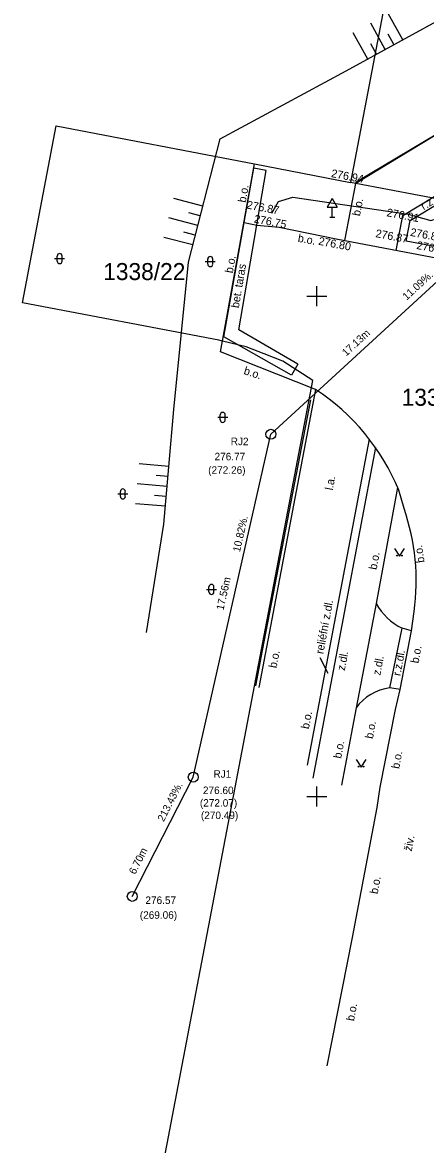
# Model space of a CAD drawing. Extents: x -601602 to -600882, y -1162594 to -1161950.
# Drawn here: x -601289.7 to -601269.6, y -1162117.4 to -1162061.3 of the extents above; entities that cross this region are included whole.
import ezdxf

# ---------------------------------------------------------------- set-up
doc = ezdxf.new("R2010")
doc.units = 0
for name, color, linetype in [('G_ZNACKY', 7, 'Continuous'), ('H_VYSKY_PREVZATE', 7, 'Continuous'), ('IS_KAN_JEDNOTNA', 7, 'Continuous'), ('IS_VO_PRELOZKA', 7, 'Continuous'), ('KN_Hranice parcel', 7, 'Continuous'), ('KN_Parcelní čísla', 7, 'Continuous'), ('Vrstva 14', 7, 'Continuous'), ('Vrstva 19', 7, 'Continuous'), ('Vrstva 22', 7, 'Continuous'), ('Vrstva 49', 7, 'Continuous'), ('Vrstva 7', 7, 'Continuous'), ('X_SOUR_KRIZKY_SEVER', 7, 'Continuous')]:
    doc.layers.add(name, color=color, linetype=linetype)

# ---------------------------------------------------------------- blocks, each defined once
blk = doc.blocks.new('POINT_DISPLAY')
blk.add_line((0, 0), (0, 0))

msp = doc.modelspace()

# ---------------------------------------------------------------- linework, layer by layer
at = {"layer": 'G_ZNACKY'}
for centre in [(-601277.302, -1162081.896), (-601281.181, -1162099.025), (-601284.233, -1162104.983)]:
    msp.add_circle(centre, 0.25, dxfattribs=at)
at = {"layer": 'IS_KAN_JEDNOTNA'}
msp.add_lwpolyline([(-601284.233, -1162104.983), (-601281.181, -1162099.025), (-601277.302, -1162081.896), (-601264.676, -1162070.309), (-601240.903, -1162074.739), (-601224.554, -1162077.728), (-601180.153, -1162087.436), (-601164.522, -1162091.613), (-601134.295, -1162101.261)], dxfattribs=at)
at = {"layer": 'IS_VO_PRELOZKA'}
msp.add_lwpolyline([(-601277.25, -1162070.85), (-601276.92, -1162070.27), (-601276.21, -1162070.04), (-601270.43, -1162070.89), (-601269.3, -1162071.21), (-601267.85, -1162070.76), (-601267.85, -1162070.76), (-601265.6, -1162071.22), (-601262.94, -1162071.88), (-601254.87, -1162073.2), (-601250.35, -1162073.86), (-601249.7, -1162074.36), (-601250.2, -1162075.96), (-601249.52, -1162074.33), (-601248.79, -1162074.18), (-601240.94, -1162075.85), (-601238.61, -1162076.29), (-601226.51, -1162078.06), (-601223.39, -1162080.54), (-601226.51, -1162078.06), (-601238.61, -1162076.29), (-601238.61, -1162076.29)], dxfattribs=at)
at = {"layer": 'KN_Hranice parcel'}
for p, q in [((-601266.06, -1162031.27), (-601273.32, -1162069.31)), ((-601279.72, -1162077.24), (-601278.12, -1162068.39)), ((-601278.12, -1162068.39), (-601273.32, -1162069.31)), ((-601273.06, -1162069.36), (-601273.32, -1162069.31)), ((-601265.78, -1162070.75), (-601273.06, -1162069.36))]:
    msp.add_line(p, q, dxfattribs=at)
for points in [[(-601238.38, -1162068.56), (-601263.78, -1162063.75), (-601273.06, -1162069.36)], [(-601279.72, -1162077.24), (-601279.91, -1162077.2), (-601289.73, -1162075.33), (-601288.05, -1162066.49), (-601278.12, -1162068.39)], [(-601288.12, -1162146.84), (-601275.21, -1162079.21), (-601276.71, -1162078.25), (-601277.63, -1162077.88), (-601278.53, -1162077.52), (-601279.72, -1162077.24)]]:
    msp.add_lwpolyline(points, dxfattribs=at)
at = {"layer": 'Vrstva 14'}
for p, q in [((-601287.993, -1162073.242), (-601287.993, -1162072.992)), ((-601287.743, -1162073.242), (-601287.743, -1162072.992)), ((-601288.118, -1162073.117), (-601287.618, -1162073.117)), ((-601280.586, -1162073.262), (-601280.086, -1162073.262)), ((-601280.461, -1162073.387), (-601280.461, -1162073.137)), ((-601280.211, -1162073.387), (-601280.211, -1162073.137)), ((-601279.835, -1162081.172), (-601279.835, -1162080.922)), ((-601279.585, -1162081.172), (-601279.585, -1162080.922)), ((-601279.96, -1162081.047), (-601279.46, -1162081.047)), ((-601284.832, -1162085.001), (-601284.832, -1162084.751)), ((-601284.582, -1162085.001), (-601284.582, -1162084.751)), ((-601284.957, -1162084.876), (-601284.457, -1162084.876)), ((-601271.12, -1162087.605), (-601270.87, -1162087.979)), ((-601270.87, -1162087.979), (-601270.62, -1162087.605)), ((-601280.526, -1162089.645), (-601280.026, -1162089.645)), ((-601280.401, -1162089.77), (-601280.401, -1162089.52)), ((-601280.151, -1162089.77), (-601280.151, -1162089.52)), ((-601273.037, -1162098.146), (-601272.787, -1162098.52)), ((-601272.787, -1162098.52), (-601272.537, -1162098.146))]:
    msp.add_line(p, q, dxfattribs=at)
for points in [[(-601270.995, -1162087.98), (-601271.02, -1162087.955), (-601270.995, -1162087.93)], [(-601270.995, -1162087.98), (-601270.995, -1162087.93), (-601270.97, -1162087.955)], [(-601270.745, -1162087.98), (-601270.77, -1162087.955), (-601270.745, -1162087.93)], [(-601270.745, -1162087.98), (-601270.745, -1162087.93), (-601270.72, -1162087.955)], [(-601272.912, -1162098.521), (-601272.937, -1162098.496), (-601272.912, -1162098.471)], [(-601272.912, -1162098.521), (-601272.912, -1162098.471), (-601272.887, -1162098.496)], [(-601272.662, -1162098.521), (-601272.687, -1162098.496), (-601272.662, -1162098.471)], [(-601272.662, -1162098.521), (-601272.662, -1162098.471), (-601272.637, -1162098.496)]]:
    msp.add_lwpolyline(points, close=True, dxfattribs=at)
for centre, start, end in [((-601287.868, -1162072.992), 0, 180), ((-601280.335, -1162073.139), 0, 180), ((-601287.868, -1162073.242), 180, 360), ((-601280.335, -1162073.389), 180, 360), ((-601279.709, -1162080.924), 0, 180), ((-601279.709, -1162081.174), 180, 360), ((-601284.705, -1162084.751), 0, 180), ((-601284.705, -1162085.001), 180, 360), ((-601280.275, -1162089.522), 0, 180), ((-601280.275, -1162089.772), 180, 360)]:
    msp.add_arc(centre, 0.125, start, end, dxfattribs=at)
at = {"layer": 'Vrstva 19'}
for p, q in [((-601274.23, -1162070.117), (-601274.48, -1162070.55)), ((-601274.23, -1162070.117), (-601273.98, -1162070.55)), ((-601274.48, -1162070.55), (-601273.98, -1162070.55)), ((-601274.23, -1162071.05), (-601274.23, -1162070.55)), ((-601274.355, -1162071.05), (-601274.105, -1162071.05))]:
    msp.add_line(p, q, dxfattribs=at)
at = {"layer": 'Vrstva 22'}
msp.add_line((-601277.74, -1162092.69), (-601278.074, -1162094.46), dxfattribs=at)
at = {"layer": 'Vrstva 49'}
msp.add_line((-601274.859, -1162093.042), (-601274.451, -1162093.824), dxfattribs=at)
at = {"layer": 'Vrstva 7'}
for p, q in [((-601273.54, -1162063.74), (-601268.18, -1162060.8)), ((-601270.705, -1162062.185), (-601271.427, -1162060.87)), ((-601272.459, -1162063.147), (-601273.18, -1162061.832)), ((-601271.582, -1162062.666), (-601272.303, -1162061.351)), ((-601272.02, -1162062.907), (-601272.309, -1162062.38)), ((-601271.144, -1162062.426), (-601271.432, -1162061.9)), ((-601279.84, -1162067.13), (-601273.54, -1162063.74)), ((-601273.03, -1162069.28), (-601263.78, -1162063.76)), ((-601270.7, -1162070.97), (-601263.28, -1162066.46)), ((-601270.34, -1162071.22), (-601263.2, -1162066.88)), ((-601281.43, -1162073.3), (-601279.84, -1162067.13)), ((-601278.91, -1162076.68), (-601277.53, -1162068.71)), ((-601278.63, -1162071.32), (-601278.15, -1162068.6)), ((-601277.53, -1162068.71), (-601278.15, -1162068.6)), ((-601273.607, -1162072.217), (-601273.03, -1162069.28)), ((-601280.707, -1162070.494), (-601282.159, -1162070.119)), ((-601280.832, -1162070.978), (-601281.413, -1162070.828)), ((-601280.956, -1162071.462), (-601282.409, -1162071.088)), ((-601279.82, -1162077.77), (-601278.63, -1162071.32)), ((-601279.65, -1162077.03), (-601278.63, -1162071.32)), ((-601278.63, -1162071.32), (-601278.003, -1162071.44)), ((-601271.028, -1162072.708), (-601270.7, -1162070.97)), ((-601270.53, -1162072.24), (-601270.34, -1162071.22)), ((-601281.081, -1162071.946), (-601281.662, -1162071.797)), ((-601278.003, -1162071.44), (-601276.89, -1162071.55)), ((-601276.89, -1162071.55), (-601273.96, -1162072.15)), ((-601281.206, -1162072.431), (-601282.658, -1162072.056)), ((-601273.96, -1162072.15), (-601268.6, -1162073.17)), ((-601268.56, -1162072.61), (-601270.53, -1162072.24)), ((-601282.16, -1162080.66), (-601281.43, -1162073.3)), ((-601275.96, -1162078.4), (-601278.91, -1162076.68)), ((-601276.27, -1162078.94), (-601279.65, -1162077.03)), ((-601275.07, -1162079.65), (-601279.82, -1162077.77)), ((-601275.96, -1162078.4), (-601276.27, -1162078.94)), ((-601275.07, -1162079.65), (-601277.901, -1162094.544)), ((-601275.32, -1162080.17), (-601277.74, -1162092.69)), ((-601282.65, -1162086.38), (-601282.16, -1162080.66)), ((-601272.38, -1162082.14), (-601275.494, -1162098.423)), ((-601272.071, -1162082.561), (-601275.21, -1162099.08)), ((-601282.404, -1162083.503), (-601283.898, -1162083.375)), ((-601282.446, -1162084.001), (-601283.044, -1162083.95)), ((-601282.489, -1162084.499), (-601283.983, -1162084.371)), ((-601270.962, -1162084.554), (-601272.04, -1162090.35)), ((-601270.64, -1162085.61), (-601270.903, -1162084.695)), ((-601282.574, -1162085.495), (-601284.069, -1162085.367)), ((-601282.532, -1162084.997), (-601283.129, -1162084.946)), ((-601283.52, -1162091.793), (-601282.65, -1162086.38)), ((-601272.04, -1162090.35), (-601273.04, -1162095.57)), ((-601270.26, -1162091.72), (-601270.14, -1162090.75)), ((-601271.35, -1162094.57), (-601270.74, -1162091.59)), ((-601270.84, -1162094.64), (-601270.26, -1162091.72)), ((-601270.26, -1162091.72), (-601270.74, -1162091.59)), ((-601270.84, -1162094.64), (-601271.35, -1162094.57)), ((-601271.06, -1162095.64), (-601270.84, -1162094.64)), ((-601273.04, -1162095.57), (-601273.77, -1162099.43)), ((-601271.83, -1162099.53), (-601271.06, -1162095.64)), ((-601271.99, -1162100.55), (-601271.83, -1162099.53)), ((-601273.22, -1162107.03), (-601271.99, -1162100.55)), ((-601274.478, -1162113.453), (-601273.22, -1162107.03))]:
    msp.add_line(p, q, dxfattribs=at)
for centre, radius, start, end in [((-601281.15, -1162088.916), 11.083, 22.3902, 56.73), ((-601280.941, -1162089.206), 10.91, 351.866, 19.2461), ((-601269.366, -1162088.848), 3.067, 209.324, 243.3824), ((-601271.083, -1162096.95), 2.395, 96.4101, 144.8168)]:
    msp.add_arc(centre, radius, start, end, dxfattribs=at)
at = {"layer": 'X_SOUR_KRIZKY_SEVER'}
for p, q in [((-601275, -1162075.5), (-601275, -1162074.5)), ((-601275.5, -1162075), (-601274.5, -1162075)), ((-601275, -1162100.5), (-601275, -1162099.5)), ((-601275.5, -1162100), (-601274.5, -1162100))]:
    msp.add_line(p, q, dxfattribs=at)

# ---------------------------------------------------------------- block references
at = {"layer": 'Vrstva 7'}
msp.add_blockref('POINT_DISPLAY', (-601279.65, -1162077.03), dxfattribs=at)

# ---------------------------------------------------------------- texts
at = {"layer": 'H_VYSKY_PREVZATE'}
for s, p in [('276.94 ', (-601274.307, -1162069.04)), ('276.87 ', (-601278.537, -1162070.61)), ('276.91 ', (-601271.532, -1162070.996)), ('276.75 ', (-601278.167, -1162071.31)), ('276.87 ', (-601272.088, -1162072.039)), ('276.88 ', (-601270.352, -1162071.976)), ('276.80 ', (-601274.946, -1162072.422)), ('276.87 ', (-601270.039, -1162072.631))]:
    msp.add_text(s, height=0.4, rotation=349.3397, dxfattribs=at).set_placement(p)
at = {"layer": 'IS_KAN_JEDNOTNA'}
for s, rotation, p in [('11.09%.', 42.5429, (-601270.509, -1162075.221)), ('17.13m', 42.5429, (-601273.537, -1162078.019)), ('10.82%.', 77.2397, (-601278.851, -1162087.802)), ('17.56m', 77.2397, (-601279.674, -1162090.709)), ('213.43%.', 62.888, (-601282.662, -1162101.277)), ('6.70m', 62.888, (-601284.093, -1162103.916))]:
    msp.add_text(s, height=0.375, rotation=rotation, dxfattribs=at).set_placement(p)
for s, p in [('RJ2', (-601279.31, -1162082.439)), ('276.77', (-601280.119, -1162083.195)), ('(272.26)', (-601280.437, -1162083.87)), ('RJ1', (-601280.174, -1162099.055)), ('276.60', (-601280.701, -1162099.872)), ('(272.07)', (-601280.853, -1162100.5)), ('(270.49)', (-601280.801, -1162101.12)), ('276.57', (-601283.577, -1162105.363)), ('(269.06)', (-601283.858, -1162106.102))]:
    msp.add_text(s, height=0.375, dxfattribs=at).set_placement(p)
at = {"layer": 'KN_Parcelní čísla'}
for s, p in [('1338/22', (-601285.688, -1162074.19)), ('1338/38', (-601270.76, -1162080.47))]:
    msp.add_text(s, height=0.85, dxfattribs=at).set_placement(p)
at = {"layer": 'Vrstva 49'}
for s, rotation, p in [('r.z.dl.(20x16)', 31.293, (-601269.66, -1162070.706)), ('l.a.', 79.2301, (-601274.208, -1162084.713)), ('b.o.', 98.5663, (-601269.611, -1162088.287)), ('b.o.', 79.4439, (-601272.015, -1162088.687)), ('reliéfní z.dl.', 79.4763, (-601274.681, -1162092.896)), ('b.o.', 79.4439, (-601269.92, -1162093.363)), ('b.o.', 78.9681, (-601277.023, -1162093.602)), ('z.dl.', 79.2301, (-601273.61, -1162093.729)), ('z.dl.', 79.2301, (-601271.83, -1162093.963)), ('r.z.dl.', 79.2301, (-601270.826, -1162093.99)), ('b.o.', 78.9681, (-601275.404, -1162096.645)), ('b.o.', 79.4439, (-601272.201, -1162097.132)), ('b.o.', 79.4439, (-601273.788, -1162098.118)), ('b.o.', 79.4439, (-601270.885, -1162098.632)), ('živ.', 79.2331, (-601270.261, -1162102.752)), ('b.o.', 79.4439, (-601271.962, -1162104.888)), ('b.o.', 79.4439, (-601273.144, -1162111.235))]:
    msp.add_text(s, height=0.4, rotation=rotation, dxfattribs=at).set_placement(p)
at = {"layer": 'Vrstva 7'}
for s, rotation, p in [('b.o.', 80.8103, (-601278.554, -1162070.338)), ('b.o.', 78.887, (-601272.847, -1162071.016)), ('b.o.', 349.2255, (-601275.976, -1162072.271)), ('b.o.', 79.2017, (-601279.215, -1162073.868)), ('bet. taras', 80.468, (-601278.907, -1162075.61)), ('b.o.', 341.9911, (-601278.693, -1162078.882))]:
    msp.add_text(s, height=0.4, rotation=rotation, dxfattribs=at).set_placement(p)

doc.saveas('drawing.dxf')
